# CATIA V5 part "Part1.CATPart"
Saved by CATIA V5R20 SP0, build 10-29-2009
Part number: Part1
Bounding box of the stored display mesh (mm): x -50.8 to 50.8, y -50.8 to 50.8, z 0 to 12.7
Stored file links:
  C:\Users\TAK SYS\Desktop\Part1.CATPart
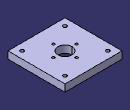
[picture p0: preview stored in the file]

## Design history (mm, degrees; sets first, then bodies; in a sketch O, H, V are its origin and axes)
Body1 (main body)
  Sketch1 on xy-plane, origin (0, 0, 0), H (1, 0, 0), V (0, 1, 0)
    point P1 (-50.8, -50.8)
    line L1 (-50.8, -50.8) -> (50.8, -50.8)
    line L2 (50.8, -50.8) -> (50.8, 50.8)
    line L3 (50.8, 50.8) -> (-50.8, 50.8)
    line L4 (-50.8, 50.8) -> (-50.8, -50.8)
    point P3 (50.8, 50.8)
    circle A1 centre (0, 0) radius 12.7
    circle A2 centre (38.1, 38.1) radius 3.302
    point P5 (38.1, 38.1)
    circle A3 centre (-38.1, -38.1) radius 3.302
    point P6 (-38.1, -38.1)
    circle A4 centre (-38.1, 38.1) radius 3.302
    point P7 (-38.1, 38.1)
    circle A5 centre (38.1, -38.1) radius 3.302
    point P8 (38.1, -38.1)
    circle A6 centre (20.6375, 0) radius 2.413
    circle A7 centre (0, 20.6375) radius 2.413
    circle A8 centre (-20.6375, 0) radius 2.413
    circle A9 centre (0, -20.6375) radius 2.413
    distance P1 V = 50.8
    distance P1 H = 50.8
    distance P3 V = 50.8
    distance P3 H = 50.8
    radius A1 = 12.7
    distance P5 V = 38.1
    distance P5 H = 38.1
    radius A2 = 3.302
    distance P6 V = 38.1
    distance P6 H = 38.1
    radius A3 = 3.302
    distance P7 V = 38.1
    distance P7 H = 38.1
    radius A4 = 3.302
    distance P8 V = 38.1
    distance P8 H = 38.1
    radius A5 = 3.302
    radius A6 = 2.413
  Pad1: profile Sketch1.L3, length 12.7
  Pocket1: profile Sketch1.A3, length 12.7
  Pocket2: profile Sketch1.A5, length 12.7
